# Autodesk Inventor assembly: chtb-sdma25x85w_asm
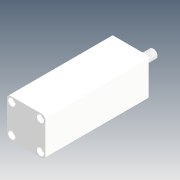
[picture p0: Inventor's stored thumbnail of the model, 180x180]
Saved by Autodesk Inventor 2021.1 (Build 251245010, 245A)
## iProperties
Company: Microsoft
Created: 2018-05
Part Number: chtb-sdma25x85w_asm
Description: STEP AP214
Document SubType Name: Assembly
Designer: user
Title: chtb-sdma25x85w_asm.STEP
Author: Windows
Revision Number: ÈÎºÎ
Sending System: SolidWorks 2015
Preprocessor: SwSTEP 2.0
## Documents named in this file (4)
- D:\Vault_2016\Projekty\Clamptek\Hydraulic\CHTB\CHTB-25\Inventor\chtb-sdma25x85w\chtb-sdma25x85w_asm.iam
- D:\Vault_2016\Projekty\Clamptek\Hydraulic\CHTB\CHTB-25\Inventor\chtb-sdma25x85w\CHTB-25QG.ipt
- D:\Vault_2016\Projekty\Clamptek\Hydraulic\CHTB\CHTB-25\Inventor\chtb-sdma25x85w\CHTB-SDMA25X85NBT.ipt
- D:\Vault_2016\Projekty\Clamptek\Hydraulic\CHTB\CHTB-25\Inventor\chtb-sdma25x85w\CHTB-SDMA25X85WHSG.ipt
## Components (3 placed, 3 different names)
1. CHTB-25QG_1
2. CHTB-SDMA25X85NBT_2
3. CHTB-SDMA25X85WHSG_3
